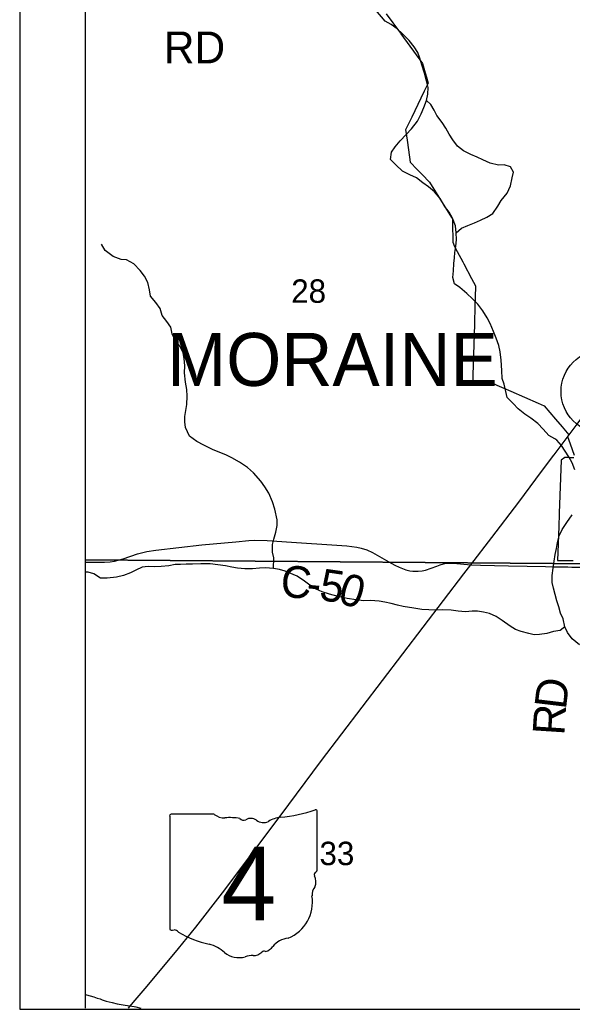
# Model space of a CAD drawing. Extents: x 0 to 34, y 0 to 22.
# Drawn here: x 2 to 2.988, y 14 to 15.768 of the extents above; entities that cross this region are included whole.
import ezdxf

# ---------------------------------------------------------------- set-up
doc = ezdxf.new("R2010")
doc.units = 0
for name, color, linetype in [('GM_X_Corporation_Text', 7, 'Continuous'), ('GM_X_County_Road', 7, 'Continuous'), ('GM_X_County_Road_Text', 7, 'Continuous'), ('GM_X_Interchange_Ramps', 7, 'Continuous'), ('GM_X_Interstate_Route', 7, 'Continuous'), ('GM_X_Minor_River', 7, 'Continuous'), ('GM_X_Section_Text', 7, 'Continuous'), ('GM_X_State_Location', 7, 'Continuous'), ('GM_X_State_Route', 7, 'Continuous'), ('GM_X_State_Shield', 7, 'Continuous'), ('GM_X_Township_Road_Text', 7, 'Continuous'), ('GM_X_Unincorporated', 7, 'Continuous'), ('SH_Data', 7, 'Continuous')]:
    doc.layers.add(name, color=color, linetype=linetype)

msp = doc.modelspace()

# ---------------------------------------------------------------- linework, layer by layer
at = {"layer": 'GM_X_County_Road'}
for points in [[(2.1171, 14.7992), (2.1391, 14.7991), (2.1513, 14.7988), (2.1614, 14.7996), (2.1694, 14.8009), (2.1848, 14.8051), (2.2106, 14.8139), (2.2272, 14.8178), (2.2433, 14.8205), (2.3254, 14.8297), (2.3865, 14.8356), (2.4097, 14.8378), (2.4196, 14.8384), (2.4424, 14.8377), (2.4858, 14.8347), (2.5666, 14.8293), (2.5845, 14.8279), (2.5936, 14.8269), (2.6027, 14.8256), (2.6106, 14.824), (2.6208, 14.8208), (2.6304, 14.816), (2.6596, 14.7996), (2.6704, 14.7936), (2.6786, 14.7898), (2.6903, 14.7855), (2.6972, 14.7836), (2.7027, 14.783), (2.7123, 14.7827), (2.7194, 14.7834), (2.7257, 14.7846), (2.7358, 14.788), (2.7456, 14.7921), (2.7517, 14.7944), (2.7578, 14.7963), (2.7625, 14.797), (2.7753, 14.7972), (2.8064, 14.7944)], [(2.8064, 14.7944), (2.8239, 14.7939), (2.8738, 14.7925), (2.9073, 14.7918), (2.9399, 14.7912)], [(2.9399, 14.7912), (2.9531, 14.7909), (2.9802, 14.7905)], [(2.9802, 14.7905), (2.9873, 14.7903), (3.0212, 14.7899)]]:
    msp.add_lwpolyline(points, dxfattribs=at)
at = {"layer": 'GM_X_Interchange_Ramps'}
for points in [[(2.6549, 15.779), (2.6805, 15.7443), (2.6814, 15.7432), (2.7203, 15.6904), (2.7238, 15.6779), (2.7271, 15.6659), (2.7301, 15.6548), (2.7233, 15.6409), (2.7173, 15.6285), (2.7008, 15.5941), (2.6899, 15.5715), (2.6908, 15.5651), (2.6931, 15.5491), (2.6982, 15.5141), (2.7108, 15.5007), (2.7193, 15.4917), (2.7324, 15.4779), (2.7722, 15.415), (2.7737, 15.4126), (2.7739, 15.4056), (2.7746, 15.3709), (2.7773, 15.363), (2.7819, 15.3544), (2.792, 15.3355), (2.7939, 15.3319), (2.8078, 15.306), (2.8148, 15.293), (2.8147, 15.2909), (2.8137, 15.2564), (2.8134, 15.2439), (2.8132, 15.2382), (2.8131, 15.2342), (2.8128, 15.2246), (2.8097, 15.1156), (2.837, 15.1213), (2.8388, 15.1216), (2.8438, 15.1195), (2.8481, 15.1176), (2.8527, 15.1156), (2.8781, 15.1044), (2.9269, 15.0831), (2.9376, 15.0784), (2.958, 15.0545), (2.9699, 15.0407), (2.9819, 15.0266), (2.9796, 15.0236), (2.9842, 15.0102), (2.9911, 14.99)], [(2.9907, 14.9854), (2.9835, 14.9857), (2.9794, 14.9859), (2.9747, 14.9862), (2.9683, 14.9812), (2.9647, 14.8866), (2.9637, 14.8616), (2.9636, 14.8568), (2.9634, 14.8536), (2.9632, 14.8481), (2.963, 14.8428), (2.9627, 14.836), (2.9625, 14.8317), (2.9612, 14.8022), (2.9892, 14.8018)]]:
    msp.add_lwpolyline(points, dxfattribs=at)
at = {"layer": 'GM_X_Interstate_Route'}
msp.add_line((2.1171, 17.2013), (2.1171, 14.0019), dxfattribs=at)
at = {"layer": 'GM_X_Minor_River'}
for points in [[(2.9566, 15.0197), (2.9457, 15.0254), (2.9361, 15.0367), (2.9265, 15.0468), (2.9138, 15.0563), (2.9029, 15.0635), (2.8914, 15.0729), (2.8822, 15.0827), (2.8714, 15.0933), (2.866, 15.1174), (2.8624, 15.1274), (2.8621, 15.1414), (2.861, 15.1601), (2.8588, 15.175), (2.8564, 15.1865), (2.8518, 15.1992), (2.8472, 15.2115), (2.8408, 15.2257), (2.8357, 15.2358), (2.8281, 15.2482), (2.8189, 15.2598), (2.8096, 15.2696), (2.7996, 15.279), (2.7869, 15.2896), (2.7772, 15.2964), (2.7741, 15.3075), (2.7752, 15.3196), (2.7763, 15.3326), (2.777, 15.3428), (2.7776, 15.3523), (2.7794, 15.3633), (2.7809, 15.3754), (2.7805, 15.3876), (2.7793, 15.4002), (2.774, 15.414), (2.7678, 15.4245), (2.7597, 15.435), (2.7517, 15.4489), (2.7414, 15.4606), (2.731, 15.47), (2.7209, 15.4772), (2.7093, 15.4859), (2.6977, 15.4915), (2.6841, 15.498), (2.6723, 15.509), (2.663, 15.5187), (2.6649, 15.5316), (2.6712, 15.5413), (2.6799, 15.5521), (2.6909, 15.5632), (2.7003, 15.5736), (2.7113, 15.587), (2.7174, 15.6002), (2.7223, 15.6118), (2.7272, 15.6242), (2.7294, 15.6352), (2.7301, 15.6474), (2.7274, 15.6592), (2.7236, 15.6727), (2.719, 15.688), (2.7155, 15.6999), (2.712, 15.7099), (2.7054, 15.72), (2.6962, 15.7313), (2.6844, 15.7434), (2.6747, 15.752), (2.6639, 15.7599), (2.6534, 15.7656), (2.6364, 15.7858)], [(2.7805, 15.3876), (2.7898, 15.3957), (2.8014, 15.4007), (2.8133, 15.4057), (2.8237, 15.41), (2.8353, 15.4154), (2.8461, 15.4219), (2.8549, 15.4353), (2.8608, 15.4451), (2.8715, 15.4585), (2.8772, 15.4716), (2.8802, 15.486), (2.8828, 15.4958), (2.8773, 15.5055), (2.866, 15.5092), (2.8557, 15.5084), (2.841, 15.5122), (2.8278, 15.5183), (2.818, 15.5227), (2.8064, 15.5273), (2.7936, 15.5341), (2.7824, 15.5424), (2.7744, 15.5537), (2.7678, 15.5637), (2.7616, 15.5749), (2.755, 15.585), (2.7455, 15.5971), (2.7408, 15.6067), (2.735, 15.6172), (2.7272, 15.6242)], [(2.4535, 14.7874), (2.4542, 14.8067), (2.4521, 14.817), (2.452, 14.8303), (2.4545, 14.8401), (2.4578, 14.8526), (2.4603, 14.8647), (2.4602, 14.8746), (2.456, 14.8937), (2.4517, 14.9067), (2.4455, 14.9224), (2.4381, 14.9336), (2.4311, 14.944), (2.4177, 14.9587), (2.4073, 14.9684), (2.393, 14.9778), (2.3791, 14.9857), (2.3685, 14.9908), (2.3575, 14.9949), (2.3443, 15.0004), (2.3293, 15.008), (2.3165, 15.0147), (2.3037, 15.024), (2.2964, 15.0394), (2.2951, 15.0497), (2.2953, 15.0596), (2.2967, 15.0702), (2.2984, 15.0808), (2.2991, 15.0956), (2.2986, 15.1074), (2.2965, 15.1208), (2.2946, 15.1372), (2.2949, 15.1501), (2.294, 15.163), (2.2919, 15.173), (2.2861, 15.1849), (2.2779, 15.1957), (2.2724, 15.2072), (2.27, 15.219), (2.263, 15.2291), (2.2544, 15.2399), (2.2509, 15.2521), (2.2435, 15.2633), (2.2338, 15.2741), (2.2318, 15.2856), (2.229, 15.2989), (2.2228, 15.3101), (2.2154, 15.3205), (2.2042, 15.3321), (2.1906, 15.3392), (2.1811, 15.3402), (2.1671, 15.3454), (2.1529, 15.3563), (2.1459, 15.3671)], [(2.9927, 14.9639), (2.9874, 14.9766), (2.9819, 14.9874), (2.9754, 14.9975), (2.9684, 15.0076), (2.9603, 15.0173), (2.9566, 15.0197)], [(3.0005, 14.6511), (2.9875, 14.6617), (2.9794, 14.673), (2.9744, 14.6834), (2.9714, 14.6975), (2.9667, 14.7079), (2.964, 14.719), (2.9604, 14.7298), (2.957, 14.7413), (2.9542, 14.7524), (2.9522, 14.7627), (2.9522, 14.7749), (2.9537, 14.7882), (2.9555, 14.8007), (2.9574, 14.8124), (2.9596, 14.8234), (2.9614, 14.8344), (2.9644, 14.8461), (2.9696, 14.8573), (2.978, 14.87), (2.9879, 14.8838)], [(2.9744, 14.6834), (2.9662, 14.6768), (2.9544, 14.6748), (2.9421, 14.6717), (2.9295, 14.6698), (2.92, 14.6693), (2.9101, 14.6715), (2.8962, 14.6753), (2.8863, 14.6786), (2.8766, 14.6846), (2.8628, 14.6949), (2.852, 14.7017), (2.8396, 14.7073), (2.8293, 14.7099), (2.8187, 14.7113), (2.8088, 14.7112), (2.797, 14.7104), (2.7841, 14.7116), (2.7712, 14.7131), (2.7567, 14.7135), (2.7438, 14.7131), (2.7316, 14.7138), (2.7187, 14.7145), (2.7043, 14.7165), (2.6857, 14.7196), (2.6751, 14.7222), (2.6638, 14.7252), (2.6528, 14.7274), (2.6426, 14.7292), (2.627, 14.7304), (2.6148, 14.73), (2.6012, 14.7315), (2.5856, 14.7339), (2.569, 14.7378), (2.5535, 14.742), (2.5407, 14.7462), (2.5298, 14.751), (2.5189, 14.7578), (2.5088, 14.7653), (2.4957, 14.7737), (2.4747, 14.783), (2.4641, 14.786), (2.4535, 14.7874), (2.4394, 14.7889), (2.4288, 14.7885), (2.4162, 14.7873), (2.4025, 14.7869), (2.3892, 14.7881), (2.379, 14.7899), (2.3676, 14.7925), (2.3543, 14.7944), (2.3407, 14.7959), (2.3239, 14.796), (2.3091, 14.7953), (2.2973, 14.7952), (2.2874, 14.7951), (2.2778, 14.795), (2.2664, 14.7926), (2.253, 14.7911), (2.2412, 14.7907), (2.2298, 14.791), (2.2187, 14.7898), (2.2075, 14.7848), (2.1979, 14.7797), (2.1856, 14.7751), (2.1729, 14.7721), (2.1561, 14.7702), (2.1443, 14.7706), (2.1324, 14.7781), (2.1225, 14.7811), (2.1171, 14.7814)], [(2.1171, 14.0263), (2.1195, 14.0258), (2.1259, 14.0237), (2.1324, 14.022), (2.1384, 14.02), (2.1437, 14.0183), (2.1471, 14.0167), (2.1547, 14.0143), (2.1649, 14.0117), (2.174, 14.0096), (2.1812, 14.0087), (2.185, 14.0078), (2.196, 14.006), (2.2044, 14.0051), (2.2078, 14.0042), (2.2162, 14.0019)]]:
    msp.add_lwpolyline(points, dxfattribs=at)
at = {"layer": 'GM_X_State_Route'}
for points in [[(2.9552, 14.991), (2.9965, 15.0459), (3.0497, 15.1165), (3.0559, 15.1247)], [(2.8064, 14.7944), (2.8438, 14.843), (2.8921, 14.9063), (2.9329, 14.9608), (2.9546, 14.9902), (2.9552, 14.991)], [(2.1945, 14.0019), (2.2028, 14.0119), (2.228, 14.0413), (2.2837, 14.1085), (2.3146, 14.1464), (2.3627, 14.208), (2.4204, 14.2846), (2.4656, 14.3452), (2.5396, 14.4448), (2.794, 14.7783), (2.8064, 14.7944)]]:
    msp.add_lwpolyline(points, dxfattribs=at)
at = {"layer": 'GM_X_State_Shield'}
for p, q in [((2.268, 14.3449), (2.268, 14.1448)), ((2.3478, 14.3483), (2.2706, 14.3483)), ((2.5317, 14.2486), (2.5317, 14.3533)), ((2.5317, 14.2486), (2.5317, 14.2486))]:
    msp.add_line(p, q, dxfattribs=at)
msp.add_lwpolyline([(2.1171, 15.7957), (2.1171, 14.8034), (3.0289, 14.7963), (3.0481, 15.7894)], close=True, dxfattribs=at)
msp.add_lwpolyline([(3.0071, 14.0019), (3.0289, 14.7963), (2.1171, 14.8034), (2.1171, 14.0019)], dxfattribs=at)
for centre, radius, start, end in [((2.271, 14.3453), 0.00305, 98.1301, 188.1301), ((2.3662, 14.3715), 0.0296, 231.6195, 271.1119), ((2.376, 14.236), 0.1064, 80.4867, 94.9883), ((2.4734, 14.2872), 0.0563, 97.3462, 120.7689), ((2.4378, 14.6211), 0.2796, 275.8445, 288.9065), ((2.5288, 14.3537), 0.00294, 351.8621, 97.738), ((2.4002, 14.3463), 0.00855, 219.7921, 297.1024), ((2.4127, 14.3232), 0.0178, 54.4667, 119.1411), ((2.4357, 14.3549), 0.0214, 233.8562, 294.8282), ((2.531, 14.2409), 0.00454, 107.944, 210.337), ((2.5021, 14.2277), 0.0273, 340.033, 23.6496), ((2.5286, 14.2482), 0.00314, 289.6038, 7.7341), ((2.5422, 14.2048), 0.0198, 136.8065, 186.9296), ((2.4534, 14.1915), 0.0699, 292.3089, 8.9858), ((2.2711, 14.1443), 0.00308, 171.9584, 258.3066), ((2.2715, 14.1648), 0.0235, 267.339, 280.6039), ((2.2763, 14.1332), 0.00848, 29.7484, 93.2717), ((2.3834, 14.313), 0.2019, 240.4129, 257.1985), ((2.3232, 14.0548), 0.0632, 47.1842, 75.836), ((2.4344, 14.1254), 0.0226, 282.8732, 323.2771), ((2.4829, 14.0886), 0.0383, 94.4031, 142.5768), ((2.3915, 14.1322), 0.0401, 230.7004, 286.2918), ((2.4147, 14.063), 0.0329, 85.6951, 111.2099), ((2.4176, 14.1172), 0.0214, 268.777, 315.5493), ((2.437, 14.0978), 0.00601, 65.7517, 132.6484)]:
    msp.add_arc(centre, radius, start, end, dxfattribs=at)
at = {"layer": 'GM_X_Unincorporated'}
msp.add_circle((3.0423, 15.104), 0.0744, dxfattribs=at)
at = {"layer": 'SH_Data'}
for p, q in [((2, 17.3211), (2, 14)), ((2, 14), (9, 14))]:
    msp.add_line(p, q, dxfattribs=at)

# ---------------------------------------------------------------- texts
at = {"layer": 'GM_X_Corporation_Text'}
msp.add_text('MORAINE', height=0.0947, rotation=0, dxfattribs=at).set_placement((2.2636, 15.114))
at = {"layer": 'GM_X_County_Road_Text'}
for s, rotation, p in [('C', 355.5579, (2.465, 14.7373)), ('5', 351.7073, (2.5338, 14.7317)), ('0', 343.3376, (2.5663, 14.7271)), ('-', 354.6529, (2.5113, 14.7337)), ('D', 83.1646, (2.9764, 14.5344)), ('R', 86.3209, (2.9735, 14.4886))]:
    msp.add_text(s, height=0.0568, rotation=rotation, dxfattribs=at).set_placement(p)
at = {"layer": 'GM_X_Section_Text'}
for s, p in [('28', (2.4854, 15.2625)), ('33', (2.5359, 14.2575))]:
    msp.add_text(s, height=0.04186, rotation=0, dxfattribs=at).set_placement(p)
at = {"layer": 'GM_X_State_Location'}
msp.add_text('4', height=0.000189, rotation=0, dxfattribs=at).set_placement((2.3684, 14.2177))
for s in ['s', 'r']:
    msp.add_text(s, height=0.000189, dxfattribs=at).set_placement((2.3969, 14.2315))
at = {"layer": 'GM_X_State_Shield'}
msp.add_text('4', height=0.1318, dxfattribs=at).set_placement((2.3607, 14.1589))
at = {"layer": 'GM_X_Township_Road_Text'}
msp.add_text('RD', height=0.05682, rotation=0, dxfattribs=at).set_placement((2.2575, 15.6906))

doc.saveas('drawing.dxf')
